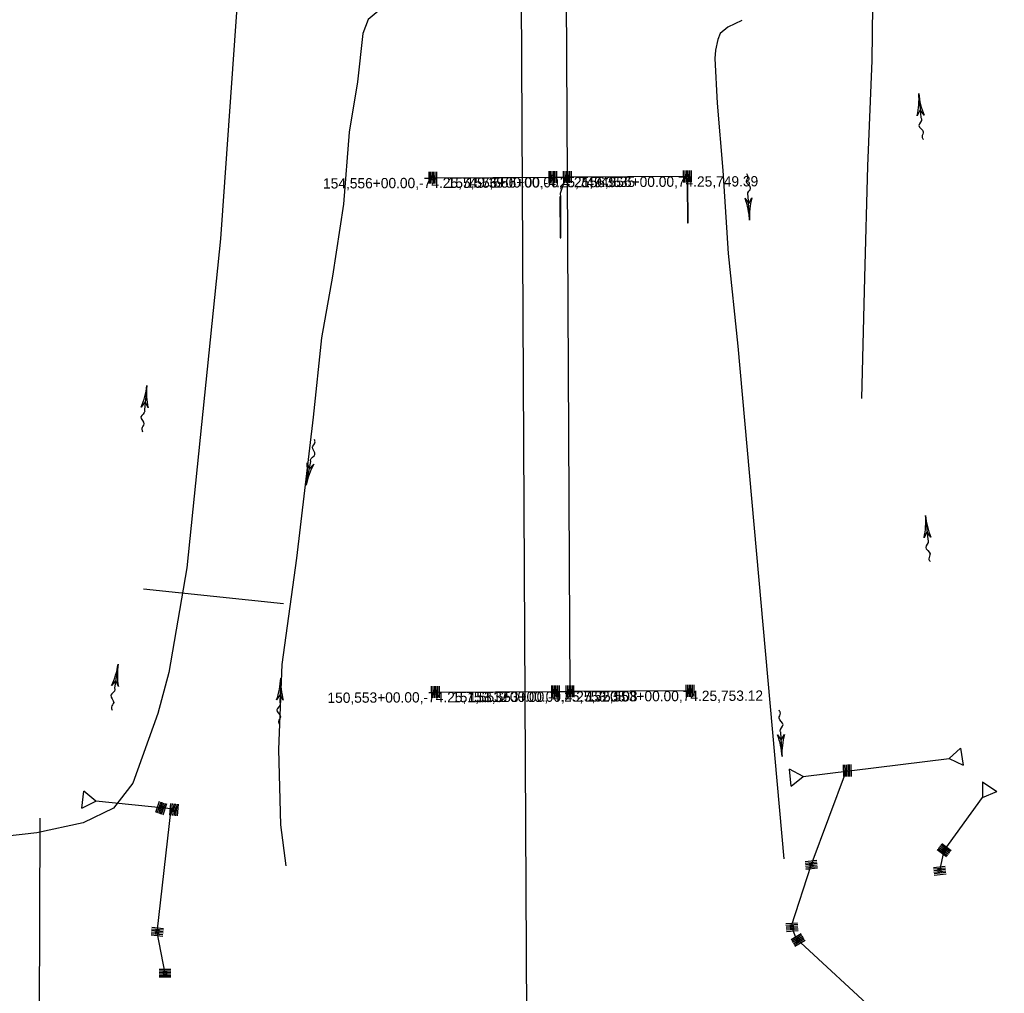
# Model space of a CAD drawing. Extents: x 593481 to 595859, y 101157 to 225994.
# Drawn here: x 594039 to 594613, y 154399 to 154967 of the extents above; entities that cross this region are included whole.
import ezdxf

# ---------------------------------------------------------------- set-up
doc = ezdxf.new("R2010")
doc.units = 0
for name, color, linetype in [('Default', 7, 'Continuous'), ('E_DTM_SpotElev', 7, 'Continuous'), ('E_PROF_GridMin', 7, 'Continuous'), ('Level 6', 7, 'Continuous'), ('P_DRN_SS_UG', 7, 'Continuous'), ('P_MAP_ContoursInter', 7, 'Continuous'), ('P_RDWY_C_and_G_H', 7, 'Continuous')]:
    doc.layers.add(name, color=color, linetype=linetype)

msp = doc.modelspace()

# ---------------------------------------------------------------- linework, layer by layer
at = {"layer": 'Default'}
msp.add_line((594334.5, 154382.75), (594308.82, 159385.62), dxfattribs=at)
at = {"layer": 'E_DTM_SpotElev'}
for p, q in [((594563.04, 154923.95), (594564.3, 154909.88)), ((594464.36, 154850.16), (594463.66, 154864.27)), ((594112.88, 154753.62), (594111.44, 154739.56)), ((594205.82, 154695.54), (594208.51, 154709.41)), ((594567, 154677.84), (594568.26, 154663.77)), ((594096.09, 154591.1), (594094.11, 154577.11)), ((594190.93, 154582.97), (594190.43, 154568.85)), ((594483.33, 154537.28), (594482.62, 154551.39))]:
    msp.add_line(p, q, dxfattribs=at)
for points in [[(594566.18, 154911.38), (594563.9, 154914.39), (594562.19, 154911.02)], [(594461.72, 154862.84), (594463.88, 154859.75), (594465.72, 154863.05)], [(594113.56, 154740.68), (594111.9, 154744.07), (594109.59, 154741.09)], [(594206.29, 154708.49), (594207.64, 154704.96), (594210.22, 154707.73)], [(594570.14, 154665.27), (594567.86, 154668.28), (594566.15, 154664.91)], [(594096.28, 154578.15), (594094.75, 154581.6), (594092.32, 154578.71)], [(594192.48, 154570.11), (594190.59, 154573.38), (594188.48, 154570.25)], [(594480.69, 154549.96), (594482.84, 154546.86), (594484.68, 154550.16)]]:
    msp.add_lwpolyline(points, dxfattribs=at)
for centre, start, end in [((594521.25, 154920.21), 347.35833, 5.12065), ((594604.83, 154927.7), 185.12065, 202.88297), ((594422.46, 154848.06), 2.86546, 20.62778), ((594506.27, 154852.26), 165.10314, 182.86546), ((594071.14, 154757.91), 336.36566, 354.12798), ((594154.62, 154749.32), 174.12798, 191.8903), ((594164.63, 154703.54), 349.00666, 6.76898), ((594247, 154687.54), 151.24434, 169.00666), ((594525.21, 154674.09), 347.35833, 5.12065), ((594608.79, 154681.58), 185.12065, 202.88297), ((594054.55, 154597), 334.15876, 351.92108), ((594137.64, 154585.21), 171.92108, 189.6834), ((594149, 154584.46), 340.19919, 357.96151), ((594232.86, 154581.48), 177.96151, 195.72383), ((594441.42, 154535.18), 2.86546, 20.62778), ((594525.23, 154539.37), 165.10314, 182.86546)]:
    msp.add_arc(centre, 41.96, start, end, dxfattribs=at)
for points in [[(594564.3, 154909.88), (594564.68, 154909.13), (594563.13, 154905.36), (594565.67, 154901.65), (594564.98, 154898.75), (594565.76, 154897.09)], [(594463.66, 154864.27), (594463.3, 154865.04), (594465, 154868.74), (594462.61, 154872.55), (594463.41, 154875.42), (594462.7, 154877.11)], [(594111.44, 154739.56), (594111.67, 154738.75), (594109.43, 154735.35), (594111.21, 154731.22), (594109.98, 154728.51), (594110.43, 154726.72)], [(594208.51, 154709.41), (594208.35, 154710.24), (594210.89, 154713.43), (594209.48, 154717.7), (594210.95, 154720.29), (594210.66, 154722.11)], [(594568.26, 154663.77), (594568.64, 154663.01), (594567.09, 154659.25), (594569.63, 154655.54), (594568.94, 154652.64), (594569.72, 154650.97)], [(594094.11, 154577.11), (594094.31, 154576.29), (594091.94, 154572.98), (594093.56, 154568.79), (594092.23, 154566.12), (594092.61, 154564.33)], [(594190.43, 154568.85), (594190.71, 154568.05), (594188.7, 154564.51), (594190.76, 154560.51), (594189.72, 154557.72), (594190.28, 154555.97)], [(594482.62, 154551.39), (594482.27, 154552.15), (594483.97, 154555.86), (594481.58, 154559.66), (594482.38, 154562.53), (594481.66, 154564.23)]]:
    msp.add_spline(points, degree=3, dxfattribs=at)
at = {"layer": 'E_PROF_GridMin'}
for p, q in [((594358.22, 154875.25), (594356.68, 155175.25)), ((594279.72, 154874.85), (594349.72, 154875.21)), ((594349.72, 154875.21), (594358.22, 154875.25)), ((594428.22, 154875.61), (594358.22, 154875.25)), ((594359.76, 154575.25), (594358.22, 154875.25)), ((594428.23, 154874.61), (594428.24, 154872.61)), ((594281.26, 154574.85), (594351.26, 154575.21)), ((594351.26, 154575.21), (594359.76, 154575.25)), ((594429.76, 154575.61), (594359.76, 154575.25)), ((594495.64, 154525.68), (594580.72, 154536.05)), ((594500.4, 154473.95), (594520.85, 154529.07)), ((594127.01, 154506.7), (594083.06, 154511.26)), ((594577.86, 154482.56), (594600.26, 154513.43)), ((594118.96, 154434.88), (594127.01, 154506.71)), ((594575.3, 154470.53), (594577.86, 154482.56)), ((594491.49, 154431.23), (594488.89, 154438.62)), ((594123.51, 154410.76), (594118.96, 154434.88)), ((594540.52, 154386.07), (594491.49, 154431.23))]:
    msp.add_line(p, q, dxfattribs=at)
for points in [[(594195.87, 155406.63), (594155.86, 154839.17), (594136.12, 154647.32), (594125.75, 154586.3), (594119.28, 154562.31), (594104.8, 154521.76), (594093.35, 154507.25), (594075.71, 154498.55), (594048.65, 154492.71), (593981.57, 154485.26), (593546.85, 154493.19), (593538.17, 154494.28), (593526.38, 154497.62), (593514.24, 154502.72), (593501.23, 154504.79), (593491.32, 154504.17), (593484.5, 154500.86), (593481.17, 154494.41)], [(594612.95, 155388.89), (594596.71, 155382.2), (594588.1, 155375.16), (594577.39, 155362.81), (594571.35, 155352.38), (594563.26, 155330.97), (594554.94, 155301.9), (594548.34, 155267.44), (594543.77, 155237.13), (594542.73, 155208.88), (594537.26, 155024.38), (594536.51, 155006.73), (594535.72, 154943.23), (594533.09, 154881.6), (594531.45, 154816.64), (594529.67, 154746.17)], [(594248.94, 154972.9), (594241.91, 154967.19), (594238.79, 154958.94), (594235.75, 154930.84), (594230.88, 154901.44), (594227.52, 154859.43), (594221.1, 154817.5), (594214.83, 154781.45), (594209.84, 154735.27), (594200.1, 154653.01), (594191.65, 154590.92), (594189.63, 154541.3), (594190.82, 154497.49), (594193.99, 154473.57)], [(594459.87, 154966.54), (594451.71, 154962.63), (594447.21, 154958.98), (594445.84, 154955.46), (594444.61, 154949.3), (594444.11, 154944.45), (594445.4, 154918.3), (594448.79, 154879.03), (594451.96, 154830.72), (594457.48, 154776.54), (594484.29, 154477.7)], [(594356.88, 154874.26), (594354.02, 154865.72), (594354.03, 154863.72)], [(594488.89, 154438.62), (594500.4, 154473.95)]]:
    msp.add_lwpolyline(points, dxfattribs=at)
at = {"layer": 'P_DRN_SS_UG'}
for p, q in [((594347.49, 154871.76), (594347.45, 154878.63)), ((594348.39, 154871.76), (594348.35, 154878.64)), ((594349.29, 154871.77), (594349.25, 154878.64)), ((594350.19, 154871.77), (594350.15, 154878.65)), ((594351.09, 154871.78), (594351.05, 154878.65)), ((594351.99, 154871.78), (594351.95, 154878.66)), ((594355.99, 154871.8), (594355.95, 154878.68)), ((594356.89, 154871.81), (594356.85, 154878.68)), ((594357.79, 154871.81), (594357.75, 154878.69)), ((594358.69, 154871.81), (594358.65, 154878.69)), ((594359.59, 154871.82), (594359.55, 154878.69)), ((594360.49, 154871.82), (594360.45, 154878.7)), ((594425.99, 154872.16), (594425.95, 154879.04)), ((594426.89, 154872.16), (594426.85, 154879.04)), ((594427.79, 154872.17), (594427.75, 154879.04)), ((594428.69, 154872.17), (594428.65, 154879.05)), ((594429.59, 154872.18), (594429.55, 154879.05)), ((594430.49, 154872.18), (594430.45, 154879.06)), ((594277.49, 154871.4), (594277.45, 154878.27)), ((594278.39, 154871.4), (594278.35, 154878.28)), ((594279.29, 154871.41), (594279.25, 154878.28)), ((594280.19, 154871.41), (594280.15, 154878.29)), ((594281.09, 154871.42), (594281.05, 154878.29)), ((594281.99, 154871.42), (594281.95, 154878.3)), ((594279.03, 154571.4), (594278.99, 154578.28)), ((594279.93, 154571.41), (594279.89, 154578.28)), ((594280.83, 154571.41), (594280.79, 154578.29)), ((594281.73, 154571.42), (594281.69, 154578.29)), ((594282.63, 154571.42), (594282.59, 154578.3)), ((594283.53, 154571.43), (594283.49, 154578.3)), ((594349.03, 154571.76), (594348.99, 154578.64)), ((594349.93, 154571.77), (594349.89, 154578.64)), ((594350.83, 154571.77), (594350.79, 154578.65)), ((594351.73, 154571.78), (594351.69, 154578.65)), ((594352.63, 154571.78), (594352.59, 154578.65)), ((594353.53, 154571.78), (594353.49, 154578.66)), ((594357.53, 154571.8), (594357.49, 154578.68)), ((594358.43, 154571.81), (594358.39, 154578.68)), ((594359.33, 154571.81), (594359.29, 154578.69)), ((594360.23, 154571.82), (594360.19, 154578.69)), ((594361.13, 154571.82), (594361.09, 154578.7)), ((594362.03, 154571.83), (594361.99, 154578.7)), ((594427.53, 154572.16), (594427.49, 154579.04)), ((594428.43, 154572.17), (594428.39, 154579.04)), ((594429.33, 154572.17), (594429.29, 154579.05)), ((594430.23, 154572.18), (594430.19, 154579.05)), ((594431.13, 154572.18), (594431.09, 154579.06)), ((594432.03, 154572.19), (594431.99, 154579.06)), ((594518.95, 154532.45), (594519.16, 154525.58)), ((594519.02, 154528.86), (594522.02, 154528.95)), ((594519.84, 154532.48), (594520.06, 154525.61)), ((594520.74, 154532.51), (594520.96, 154525.63)), ((594521.64, 154532.53), (594521.86, 154525.66)), ((594522.54, 154532.56), (594522.76, 154525.69)), ((594523.44, 154532.59), (594523.66, 154525.72)), ((594118.1, 154504.73), (594120.32, 154511.24)), ((594118.95, 154504.44), (594121.17, 154510.94)), ((594119.8, 154504.15), (594122.03, 154510.65)), ((594120.65, 154503.86), (594122.88, 154510.36)), ((594121.5, 154503.57), (594123.73, 154510.07)), ((594122.35, 154503.27), (594124.58, 154509.78)), ((594126.77, 154509.91), (594126.06, 154503.07)), ((594127.66, 154509.82), (594126.95, 154502.98)), ((594128.56, 154509.72), (594127.85, 154502.89)), ((594129.45, 154509.63), (594128.74, 154502.79)), ((594130.35, 154509.54), (594129.64, 154502.7)), ((594131.24, 154509.45), (594130.53, 154502.61)), ((594579.3, 154478.71), (594573.76, 154482.79)), ((594579.83, 154479.44), (594574.3, 154483.51)), ((594580.37, 154480.16), (594574.83, 154484.24)), ((594580.9, 154480.89), (594575.36, 154484.96)), ((594581.43, 154481.61), (594575.89, 154485.69)), ((594581.97, 154482.34), (594576.43, 154486.41)), ((594503.56, 154476.57), (594496.73, 154475.8)), ((594503.66, 154475.68), (594496.83, 154474.91)), ((594503.76, 154474.79), (594496.93, 154474.02)), ((594503.86, 154473.89), (594497.03, 154473.12)), ((594503.96, 154473), (594497.13, 154472.23)), ((594504.06, 154472.1), (594497.23, 154471.33)), ((594578.47, 154473.14), (594571.64, 154472.4)), ((594578.57, 154472.24), (594571.73, 154471.5)), ((594578.67, 154471.35), (594571.83, 154470.61)), ((594578.76, 154470.45), (594571.93, 154469.71)), ((594578.86, 154469.56), (594572.02, 154468.82)), ((594578.96, 154468.66), (594572.12, 154467.92)), ((594122.51, 154435.95), (594115.67, 154436.64)), ((594122.6, 154436.85), (594115.76, 154437.53)), ((594492.37, 154440.14), (594485.52, 154439.61)), ((594492.44, 154439.24), (594485.59, 154438.71)), ((594492.51, 154438.34), (594485.66, 154437.81)), ((594492.58, 154437.45), (594485.72, 154436.92)), ((594492.65, 154436.55), (594485.79, 154436.02)), ((594122.15, 154432.37), (594115.31, 154433.06)), ((594122.24, 154433.27), (594115.4, 154433.95)), ((594122.33, 154434.16), (594115.49, 154434.85)), ((594122.42, 154435.06), (594115.58, 154435.74)), ((594492.72, 154435.65), (594485.86, 154435.12)), ((594494.5, 154433.8), (594488.56, 154430.32)), ((594494.95, 154433.02), (594489.02, 154429.55)), ((594495.41, 154432.24), (594489.47, 154428.77)), ((594495.86, 154431.47), (594489.93, 154427.99)), ((594496.31, 154430.69), (594490.38, 154427.22)), ((594496.77, 154429.91), (594490.84, 154426.44)), ((594126.93, 154413.03), (594120.06, 154413)), ((594126.94, 154412.13), (594120.06, 154412.1)), ((594126.94, 154411.23), (594120.07, 154411.2)), ((594126.95, 154410.33), (594120.07, 154410.3)), ((594126.95, 154409.43), (594120.08, 154409.4)), ((594126.96, 154408.53), (594120.08, 154408.5))]:
    msp.add_line(p, q, dxfattribs=at)
for points in [[(594280.73, 154873.85), (594280.72, 154875.85), (594278.72, 154875.84), (594278.73, 154873.84)], [(594350.73, 154874.21), (594350.72, 154876.21), (594348.72, 154876.2), (594348.73, 154874.2)], [(594359.23, 154874.26), (594359.22, 154876.26), (594357.22, 154876.24), (594357.23, 154874.24)], [(594429.23, 154874.61), (594429.22, 154876.61), (594427.22, 154876.6), (594427.23, 154874.6)], [(594428.12, 154848.61), (594428.6, 154848.61), (594428.47, 154872.61), (594428, 154872.61)], [(594353.92, 154839.72), (594354.39, 154839.72), (594354.27, 154863.72), (594353.79, 154863.72)], [(594282.27, 154573.86), (594282.26, 154575.86), (594280.26, 154575.85), (594280.27, 154573.85)], [(594352.27, 154574.22), (594352.26, 154576.22), (594350.26, 154576.21), (594350.27, 154574.21)], [(594360.77, 154574.26), (594360.76, 154576.26), (594358.76, 154576.25), (594358.77, 154574.25)], [(594430.77, 154574.62), (594430.76, 154576.62), (594428.76, 154576.61), (594428.77, 154574.61)], [(594121.96, 154505.98), (594122.61, 154507.88), (594120.72, 154508.52), (594120.07, 154506.63)], [(594127.76, 154507.36), (594127.55, 154505.37), (594129.54, 154505.16), (594129.75, 154507.15)], [(594579.26, 154482.78), (594577.65, 154483.96), (594576.47, 154482.35), (594578.08, 154481.16)], [(594501.28, 154475.06), (594499.29, 154474.84), (594499.51, 154472.85), (594501.5, 154473.07)], [(594576.18, 154471.63), (594574.19, 154471.42), (594574.41, 154469.43), (594576.4, 154469.64)], [(594490.04, 154438.7), (594488.04, 154438.55), (594488.2, 154436.56), (594490.19, 154436.71)], [(594120.05, 154435.85), (594118.06, 154436.05), (594117.86, 154434.06), (594119.85, 154433.86)], [(594493.02, 154431.49), (594491.3, 154430.48), (594492.31, 154428.75), (594494.03, 154429.76)], [(594124.5, 154411.77), (594122.5, 154411.76), (594122.51, 154409.76), (594124.51, 154409.77)]]:
    msp.add_lwpolyline(points, close=True, dxfattribs=at)
at = {"layer": 'P_MAP_ContoursInter'}
for p, q in [((594111.01, 154635.04), (594192.63, 154626.58)), ((594050.07, 154353.52), (594050.61, 154501.37))]:
    msp.add_line(p, q, dxfattribs=at)
at = {"layer": 'P_RDWY_C_and_G_H'}
for p, q in [((594587.38, 154542.13), (594580.72, 154536.05)), ((594587.38, 154542.13), (594588.89, 154532.25)), ((594580.72, 154536.05), (594588.89, 154532.25)), ((594495.64, 154525.68), (594487.64, 154529.84)), ((594488.73, 154519.9), (594487.64, 154529.84)), ((594488.73, 154519.9), (594495.64, 154525.68)), ((594075.06, 154507.18), (594076.16, 154517.12)), ((594083.06, 154511.32), (594076.16, 154517.12)), ((594600.31, 154522.45), (594600.26, 154513.43)), ((594600.26, 154513.43), (594608.6, 154516.86)), ((594600.31, 154522.45), (594608.6, 154516.86)), ((594075.06, 154507.18), (594083.06, 154511.32))]:
    msp.add_line(p, q, dxfattribs=at)

# ---------------------------------------------------------------- texts
at = {"layer": 'Level 6'}
for s, p in [('154,556+00.00,-74.25,749.39', (594215.65, 154868.52)), ('155,556+00.00,-4.25,749.35', (594288.34, 154868.89)), ('157,556+00.00,4.25,749.35', (594299.3, 154868.95)), ('156,556+00.00,74.25,749.39', (594366.6, 154869.29)), ('150,553+00.00,-74.25,753.12', (594218.23, 154568.53)), ('151,553+00.00,-4.25,753.08', (594290.92, 154568.9)), ('153,553+00.00,4.25,753.08', (594300.65, 154568.95)), ('152,553+00.00,74.25,753.12', (594369.42, 154569.3))]:
    msp.add_text(s, height=6, rotation=0.29409, dxfattribs=at).set_placement(p)

doc.saveas('drawing.dxf')
